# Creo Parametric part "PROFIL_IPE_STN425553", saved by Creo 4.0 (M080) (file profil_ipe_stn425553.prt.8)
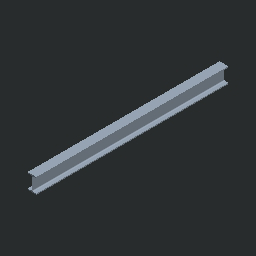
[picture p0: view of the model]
Units: millimeter Kilogram Sec (mmKs); MM, KILOGRAM, SECS
Materials in the file: OCEL_N

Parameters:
  MFG_WP_MATERIAL = "OCEL"
  NAZOV = "PROFIL_IPE_STN425553"
  NORMA = "STN 42 4553"
  PTC_MATERIAL_NAME = "OCEL_N"

Other parameters: HMOTNOST, HUSTOTA, D6, D2, D7

Created from: IPE.PRT

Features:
  1. datum plane "DTM1"
  2. datum plane "DTM2"
  3. datum plane "DTM3"

Layers: 1, 2, 3, 4, 5, 6, 7, 8, 9, 10, 11, 12, 13, 14, 15, 16, 17, 18, 19, 20, 21, 22, 23, 24, 25, 26, 27, 28, 29, 30, 31, 32

Family table entries: GENERIC, PROFIL_IPE_80, PROFIL_IPE_STN425553, value(d_val), 2/G, value(i_val), PROFIL_IPE_100, PROFIL_IPE_STN425553, !/Y, PROFIL_IPE_120, PROFIL_IPE_STN425553, !/^, 2/P, PROFIL_IPE_140, PROFIL_IPE_STN425553, PROFIL_IPE_160, PROFIL_IPE_STN425553, !/d, 2/", PROFIL_IPE_180, PROFIL_IPE_STN425553, 2/ , 2/", PROFIL_IPE_200, PROFIL_IPE_STN425553, !/i, 2/Y, 2/!, 2/(, PROFIL_IPE_220, PROFIL_IPE_STN425553, 2/(, PROFIL_IPE_240, PROFIL_IPE_STN425553, !/n, 2/^, 2/., PROFIL_IPE_270, PROFIL_IPE_STN425553, 2/.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

Surfaces: 14 plane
